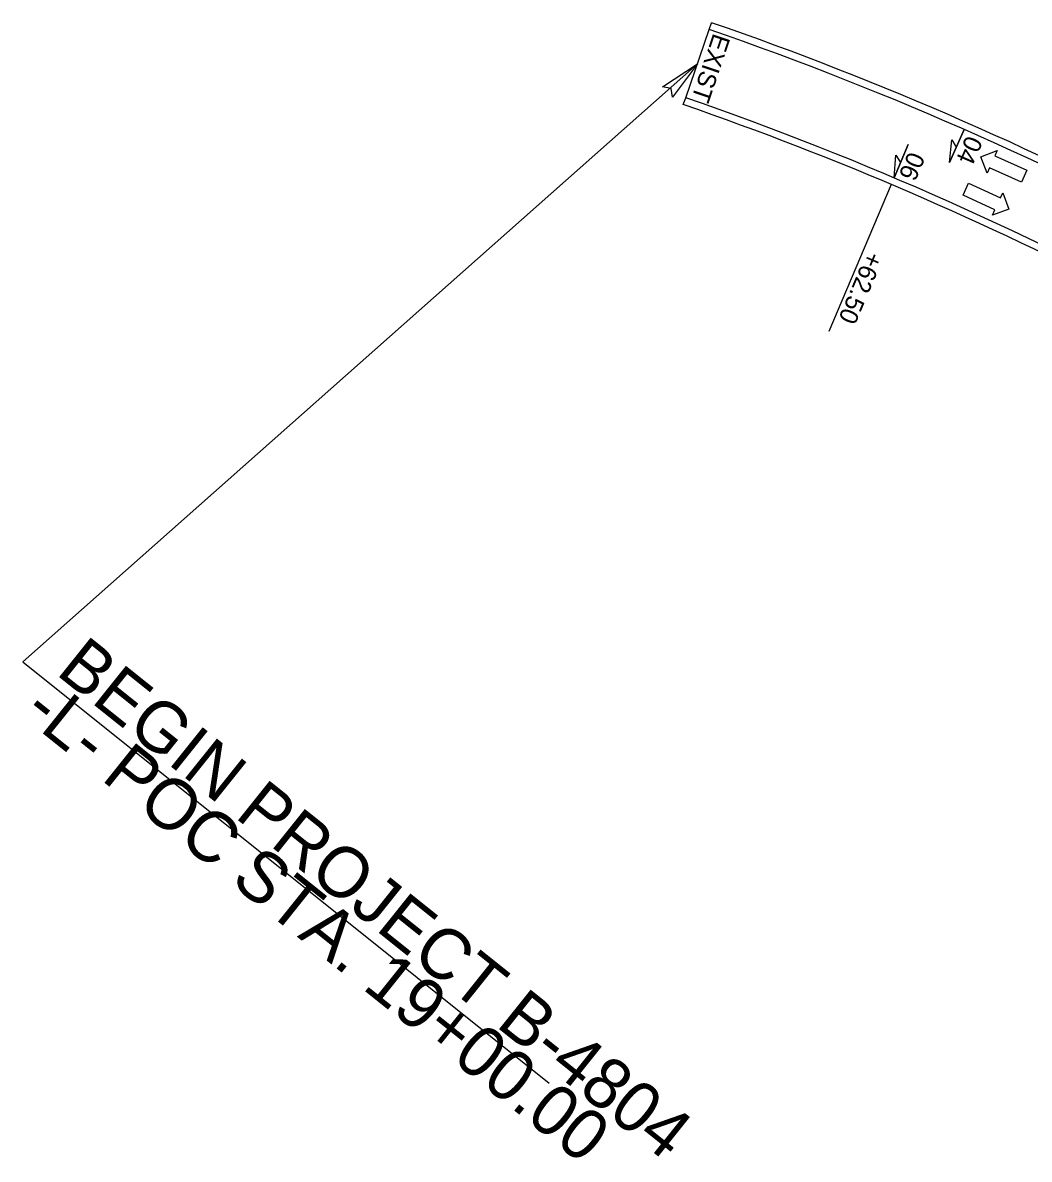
# Model space of a CAD drawing. Extents: x 1734344 to 1735097, y 915059 to 915850.
# Drawn here: x 1734343.9 to 1734622.6, y 915508 to 915822.7 of the extents above; entities that cross this region are included whole.
import ezdxf

# ---------------------------------------------------------------- set-up
doc = ezdxf.new("R2010")
doc.units = 0
for name, color, linetype in [('Prop Dimension Text', 7, 'Continuous'), ('Prop DSN Text', 7, 'Continuous'), ('Prop EOT', 7, 'Continuous'), ('Prop Lane Arrow CELL', 7, 'Continuous'), ('Prop Paved Shoulder', 7, 'Continuous'), ('Prop Superelevation  Arrow CELL', 7, 'Continuous'), ('Prop Superelevation Label', 7, 'Continuous')]:
    doc.layers.add(name, color=color, linetype=linetype)

msp = doc.modelspace()

# ---------------------------------------------------------------- linework, layer by layer
at = {"layer": 'Prop Dimension Text'}
msp.add_line((1734584.42, 915777.94), (1734567.17, 915737.24), dxfattribs=at)
at = {"layer": 'Prop DSN Text'}
for q in [(1734530.77, 915811.4), (1734489.71, 915529.06)]:
    msp.add_line((1734343.94, 915645.72), q, dxfattribs=at)
msp.add_lwpolyline([(1734521.12, 915805), (1734530.77, 915811.4), (1734523.88, 915802.1), (1734523.51, 915804.51)], close=True, dxfattribs=at)
at = {"layer": 'Prop EOT'}
msp.add_line((1734527.51, 915801.95), (1734534.04, 915820.85), dxfattribs=at)
for radius in [925, 905]:
    msp.add_arc((1734232.02, 914946.54), radius, 51.14521, 70.94317, dxfattribs=at)
at = {"layer": 'Prop Lane Arrow CELL'}
for points in [[(1734620.48, 915778.62), (1734611.64, 915782.59), (1734610.98, 915781.12), (1734609.26, 915785.64), (1734613.79, 915787.36), (1734613.13, 915785.89), (1734621.97, 915781.92)], [(1734605.86, 915778.3), (1734614.64, 915774.2), (1734615.32, 915775.66), (1734616.98, 915771.11), (1734612.43, 915769.46), (1734613.11, 915770.92), (1734604.33, 915775.02)]]:
    msp.add_lwpolyline(points, close=True, dxfattribs=at)
at = {"layer": 'Prop Paved Shoulder'}
for p, q in [((1734534.04, 915820.85), (1734534.69, 915822.74)), ((1734526.85, 915800.06), (1734527.51, 915801.95))]:
    msp.add_line(p, q, dxfattribs=at)
for radius, start in [(927, 61.70734), (903, 62.39682)]:
    msp.add_arc((1734232.02, 914946.54), radius, start, 70.94317, dxfattribs=at)
at = {"layer": 'Prop Superelevation  Arrow CELL'}
for p, q in [((1734600.58, 915784.03), (1734604.61, 915793.19)), ((1734585.2, 915779.78), (1734589.1, 915788.99))]:
    msp.add_line(p, q, dxfattribs=at)
for points in [[(1734600.58, 915784.03), (1734601.17, 915790.33), (1734602.44, 915788.27)], [(1734585.2, 915779.78), (1734585.7, 915786.09), (1734587.01, 915784.04)]]:
    msp.add_lwpolyline(points, close=True, dxfattribs=at)
at = {"layer": 'Prop Superelevation Label'}
for p, q in [((1734604.61, 915793.19), (1734600.58, 915784.03)), ((1734589.1, 915788.99), (1734585.2, 915779.78))]:
    msp.add_line(p, q, dxfattribs=at)

# ---------------------------------------------------------------- texts
at = {"layer": 'Prop Dimension Text'}
msp.add_text('+62.50', height=5, rotation=247.0295, dxfattribs=at).set_placement((1734577.78, 915759.72))
at = {"layer": 'Prop DSN Text'}
for s, p in [('BEGIN PROJECT B-4804', (1734352.81, 915642.46)), ('-L- POC STA. 19+00.00', (1734343.44, 915630.75))]:
    msp.add_text(s, height=14, rotation=321.3297, dxfattribs=at).set_placement(p)
at = {"layer": 'Prop Superelevation Label'}
for s, rotation, p in [('EXIST', 251.3034, (1734535.21, 915820.05)), ('04', 246.2468, (1734605.33, 915791.82)), ('06', 247.0295, (1734589.33, 915787.35))]:
    msp.add_text(s, height=5, rotation=rotation, dxfattribs=at).set_placement(p)

doc.saveas('drawing.dxf')
